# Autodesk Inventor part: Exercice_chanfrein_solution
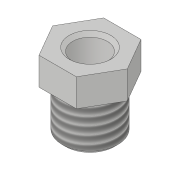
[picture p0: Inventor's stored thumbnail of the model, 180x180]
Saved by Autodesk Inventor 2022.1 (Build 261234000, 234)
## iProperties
Created: 2018-06
Part Number: Exercice_chanfrein_solution
Material: Générique
Document SubType Name: Modeling
Designer: Fabian Perrée
Density: 1 g/cm^3
Appearance: Par défaut
Mass: 1.41826 g
Surface Area: 12.5956 cm^2
Volume: 1.41826 cm^3
Author: Fabian Perrée
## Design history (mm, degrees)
sketch "Esquisse1"
  geometry: C1 r 6 at (0, 0); C2 r 3.75 at (0, 0); 1 further point
  constraints: 2 centre point, 2 coincident
  dimensions: "d0" = 12 diameter of C1; "d1" = 7.5 diameter of C2
extrude "Extrusion1" new body sketch "Esquisse1" distance "d2" = 16; taper "d3" = 0 deg
sketch "Esquisse2"
  geometry: L1 (4.041, -7)-(-4.041, -7); L2 (-4.041, -7)-(-8.083, 0); L3 (-8.083, 0)-(-4.041, 7); L4 (-4.041, 7)-(4.041, 7); L5 (4.041, 7)-(8.083, 0); L6 (8.083, 0)-(4.041, -7); C1 r 3.75 at (0, 0) reference; C2 r 6 at (0, 0) reference; 1 further point
  constraints: 12 end point, 1 coincident, 1 horizontal, 13 other
  dimensions: "d4" = 14 distance between parallel lines of L4 L1
extrude "Extrusion2" join sketch "Esquisse2" distance "d5" = 6; taper "d6" = 0 deg
chamfer "Chanfrein1" distance "d7" = 0.75; stored, may be unused: second distance "d8" = 2, angle "d9" = 45 deg
feature "Filetage1" dims "d10" = 10, "d11" = 0
node "Solide1"
